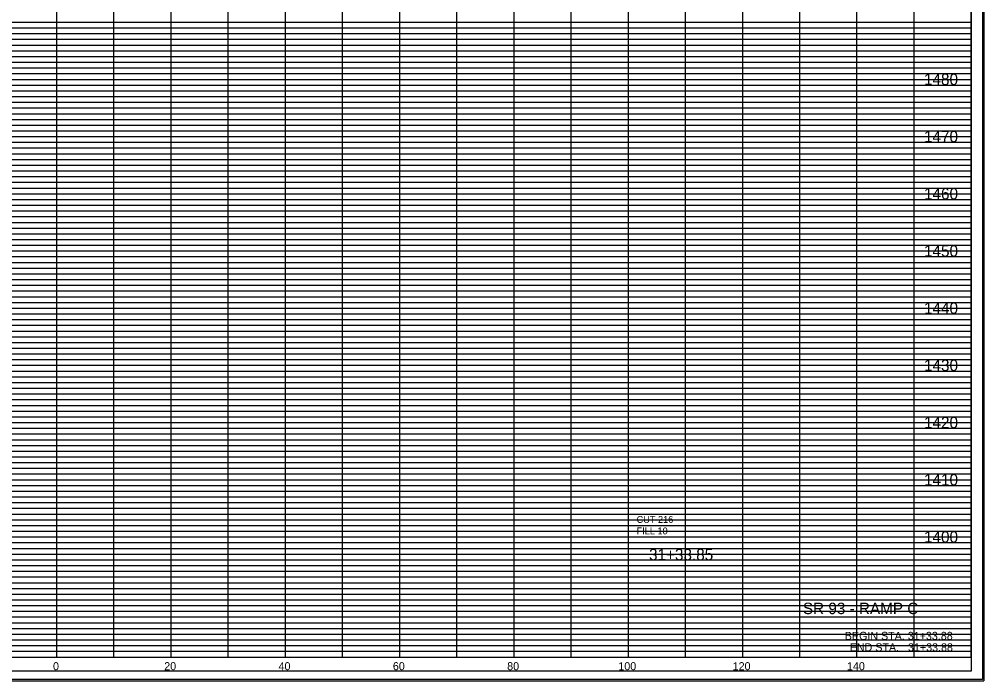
# Model space of a CAD drawing. Extents: x 980 to 2064, y 978 to 2267.
# Drawn here: x 1153.4 to 1322.2, y 1515.9 to 1631.5 of the extents above; entities that cross this region are included whole.
import ezdxf

# ---------------------------------------------------------------- set-up
doc = ezdxf.new("R2010")
doc.units = 0
for name, color, linetype in [('Default', 7, 'Continuous'), ('DESIGN - SHEET - Corner Text', 7, 'Continuous'), ('DESIGN - SHEET - Light Grid', 7, 'Continuous'), ('DESIGN - SHEET - Linework', 7, 'Continuous'), ('DESIGN - SHEET - Plot Shape', 7, 'Continuous'), ('DESIGN - TYPICAL - Text', 7, 'Continuous')]:
    doc.layers.add(name, color=color, linetype=linetype)

# ---------------------------------------------------------------- blocks, each defined once
blk = doc.blocks.new('XSTSHT')
at = {"layer": 'DESIGN - SHEET - Light Grid'}
for p, q in [((8, 11.1), (16, 11.1)), ((16, 11.1), (24, 11.1)), ((24, 11.1), (32, 11.1)), ((8, 10.9), (16, 10.9)), ((8, 10.8), (16, 10.8)), ((16, 10.9), (24, 10.9)), ((16, 10.8), (24, 10.8)), ((24, 10.9), (32, 10.9)), ((24, 10.8), (32, 10.8)), ((8, 10.7), (16, 10.7)), ((16, 10.7), (24, 10.7)), ((24, 10.7), (32, 10.7)), ((8, 10.6), (16, 10.6)), ((8, 10.5), (16, 10.5)), ((16, 10.6), (24, 10.6)), ((16, 10.5), (24, 10.5)), ((24, 10.6), (32, 10.6)), ((24, 10.5), (32, 10.5)), ((8, 10.4), (16, 10.4)), ((8, 10.3), (16, 10.3)), ((16, 10.4), (24, 10.4)), ((16, 10.3), (24, 10.3)), ((24, 10.4), (32, 10.4)), ((24, 10.3), (32, 10.3)), ((8, 10.2), (16, 10.2)), ((16, 10.2), (24, 10.2)), ((24, 10.2), (32, 10.2)), ((8, 10.1), (16, 10.1)), ((16, 10.1), (24, 10.1)), ((24, 10.1), (32, 10.1)), ((8, 9.9), (16, 9.9)), ((8, 9.8), (16, 9.8)), ((16, 9.9), (24, 9.9)), ((16, 9.8), (24, 9.8)), ((24, 9.9), (32, 9.9)), ((24, 9.8), (32, 9.8)), ((8, 9.7), (16, 9.7)), ((16, 9.7), (24, 9.7)), ((24, 9.7), (32, 9.7)), ((8, 9.6), (16, 9.6)), ((8, 9.5), (16, 9.5)), ((16, 9.6), (24, 9.6)), ((16, 9.5), (24, 9.5)), ((24, 9.6), (32, 9.6)), ((24, 9.5), (32, 9.5)), ((8, 9.4), (16, 9.4)), ((8, 9.3), (16, 9.3)), ((16, 9.4), (24, 9.4)), ((16, 9.3), (24, 9.3)), ((24, 9.4), (32, 9.4)), ((24, 9.3), (32, 9.3)), ((8, 9.2), (16, 9.2)), ((16, 9.2), (24, 9.2)), ((24, 9.2), (32, 9.2)), ((8, 9.1), (16, 9.1)), ((16, 9.1), (24, 9.1)), ((24, 9.1), (32, 9.1)), ((8, 8.9), (16, 8.9)), ((8, 8.8), (16, 8.8)), ((16, 8.9), (24, 8.9)), ((16, 8.8), (24, 8.8)), ((24, 8.9), (32, 8.9)), ((24, 8.8), (32, 8.8)), ((8, 8.7), (16, 8.7)), ((16, 8.7), (24, 8.7)), ((24, 8.7), (32, 8.7)), ((8, 8.6), (16, 8.6)), ((8, 8.5), (16, 8.5)), ((16, 8.6), (24, 8.6)), ((16, 8.5), (24, 8.5)), ((24, 8.6), (32, 8.6)), ((24, 8.5), (32, 8.5)), ((8, 8.4), (16, 8.4)), ((8, 8.3), (16, 8.3)), ((16, 8.4), (24, 8.4)), ((16, 8.3), (24, 8.3)), ((24, 8.4), (32, 8.4)), ((24, 8.3), (32, 8.3)), ((8, 8.2), (16, 8.2)), ((8, 8.1), (16, 8.1)), ((16, 8.2), (24, 8.2)), ((16, 8.1), (24, 8.1)), ((24, 8.2), (32, 8.2)), ((24, 8.1), (32, 8.1)), ((8, 7.9), (16, 7.9)), ((8, 7.8), (16, 7.8)), ((16, 7.9), (24, 7.9)), ((16, 7.8), (24, 7.8)), ((24, 7.9), (32, 7.9)), ((24, 7.8), (32, 7.8)), ((8, 7.7), (16, 7.7)), ((8, 7.6), (16, 7.6)), ((16, 7.7), (24, 7.7)), ((16, 7.6), (24, 7.6)), ((24, 7.7), (32, 7.7)), ((24, 7.6), (32, 7.6)), ((8, 7.5), (16, 7.5)), ((16, 7.5), (24, 7.5)), ((24, 7.5), (32, 7.5)), ((8, 7.4), (16, 7.4)), ((8, 7.3), (16, 7.3)), ((16, 7.4), (24, 7.4)), ((16, 7.3), (24, 7.3)), ((24, 7.4), (32, 7.4)), ((24, 7.3), (32, 7.3)), ((8, 7.2), (16, 7.2)), ((8, 7.1), (16, 7.1)), ((16, 7.2), (24, 7.2)), ((16, 7.1), (24, 7.1)), ((24, 7.2), (32, 7.2)), ((24, 7.1), (32, 7.1)), ((8, 6.9), (16, 6.9)), ((8, 6.8), (16, 6.8)), ((16, 6.9), (24, 6.9)), ((16, 6.8), (24, 6.8)), ((24, 6.9), (32, 6.9)), ((24, 6.8), (32, 6.8)), ((8, 6.7), (16, 6.7)), ((8, 6.6), (16, 6.6)), ((16, 6.7), (24, 6.7)), ((16, 6.6), (24, 6.6)), ((24, 6.7), (32, 6.7)), ((24, 6.6), (32, 6.6)), ((8, 6.5), (16, 6.5)), ((16, 6.5), (24, 6.5)), ((24, 6.5), (32, 6.5)), ((8, 6.4), (16, 6.4)), ((8, 6.3), (16, 6.3)), ((16, 6.4), (24, 6.4)), ((16, 6.3), (24, 6.3)), ((24, 6.4), (32, 6.4)), ((24, 6.3), (32, 6.3)), ((8, 6.2), (16, 6.2)), ((8, 6.1), (16, 6.1)), ((16, 6.2), (24, 6.2)), ((16, 6.1), (24, 6.1)), ((24, 6.2), (32, 6.2)), ((24, 6.1), (32, 6.1)), ((8, 5.9), (16, 5.9)), ((8, 5.8), (16, 5.8)), ((16, 5.9), (24, 5.9)), ((16, 5.8), (24, 5.8)), ((24, 5.9), (32, 5.9)), ((24, 5.8), (32, 5.8)), ((8, 5.7), (16, 5.7)), ((8, 5.6), (16, 5.6)), ((16, 5.7), (24, 5.7)), ((16, 5.6), (24, 5.6)), ((24, 5.7), (32, 5.7)), ((24, 5.6), (32, 5.6)), ((8, 5.5), (16, 5.5)), ((8, 5.4), (16, 5.4)), ((16, 5.5), (24, 5.5)), ((16, 5.4), (24, 5.4)), ((24, 5.5), (32, 5.5)), ((24, 5.4), (32, 5.4)), ((8, 5.3), (16, 5.3)), ((16, 5.3), (24, 5.3)), ((24, 5.3), (32, 5.3)), ((8, 5.2), (16, 5.2)), ((8, 5.1), (16, 5.1)), ((16, 5.2), (24, 5.2)), ((16, 5.1), (24, 5.1)), ((24, 5.2), (32, 5.2)), ((24, 5.1), (32, 5.1)), ((8, 4.9), (16, 4.9)), ((16, 4.9), (24, 4.9)), ((24, 4.9), (32, 4.9)), ((8, 4.8), (16, 4.8)), ((16, 4.8), (24, 4.8)), ((24, 4.8), (32, 4.8)), ((8, 4.7), (16, 4.7)), ((8, 4.6), (16, 4.6)), ((16, 4.7), (24, 4.7)), ((16, 4.6), (24, 4.6)), ((24, 4.7), (32, 4.7)), ((24, 4.6), (32, 4.6)), ((8, 4.5), (16, 4.5)), ((8, 4.4), (16, 4.4)), ((16, 4.5), (24, 4.5)), ((16, 4.4), (24, 4.4)), ((24, 4.5), (32, 4.5)), ((24, 4.4), (32, 4.4)), ((8, 4.3), (16, 4.3)), ((16, 4.3), (24, 4.3)), ((24, 4.3), (32, 4.3)), ((8, 4.2), (16, 4.2)), ((8, 4.1), (16, 4.1)), ((16, 4.2), (24, 4.2)), ((16, 4.1), (24, 4.1)), ((24, 4.2), (32, 4.2)), ((24, 4.1), (32, 4.1)), ((8, 3.9), (16, 3.9)), ((16, 3.9), (24, 3.9)), ((24, 3.9), (32, 3.9)), ((8, 3.8), (16, 3.8)), ((16, 3.8), (24, 3.8)), ((24, 3.8), (32, 3.8)), ((8, 3.7), (16, 3.7)), ((8, 3.6), (16, 3.6)), ((16, 3.7), (24, 3.7)), ((16, 3.6), (24, 3.6)), ((24, 3.7), (32, 3.7)), ((24, 3.6), (32, 3.6)), ((8, 3.5), (16, 3.5)), ((8, 3.4), (16, 3.4)), ((16, 3.5), (24, 3.5)), ((16, 3.4), (24, 3.4)), ((24, 3.5), (32, 3.5)), ((24, 3.4), (32, 3.4)), ((8, 3.3), (16, 3.3)), ((16, 3.3), (24, 3.3)), ((24, 3.3), (32, 3.3)), ((8, 3.2), (16, 3.2)), ((8, 3.1), (16, 3.1)), ((16, 3.2), (24, 3.2)), ((16, 3.1), (24, 3.1)), ((24, 3.2), (32, 3.2)), ((24, 3.1), (32, 3.1)), ((8, 2.9), (16, 2.9)), ((16, 2.9), (24, 2.9)), ((24, 2.9), (32, 2.9)), ((8, 2.8), (16, 2.8)), ((8, 2.7), (16, 2.7)), ((16, 2.8), (24, 2.8)), ((16, 2.7), (24, 2.7)), ((24, 2.8), (32, 2.8)), ((24, 2.7), (32, 2.7)), ((8, 2.6), (16, 2.6)), ((16, 2.6), (24, 2.6)), ((24, 2.6), (32, 2.6)), ((8, 2.5), (16, 2.5)), ((8, 2.4), (16, 2.4)), ((16, 2.5), (24, 2.5)), ((16, 2.4), (24, 2.4)), ((24, 2.5), (32, 2.5)), ((24, 2.4), (32, 2.4)), ((8, 2.3), (16, 2.3)), ((8, 2.2), (16, 2.2)), ((16, 2.3), (24, 2.3)), ((16, 2.2), (24, 2.2)), ((24, 2.3), (32, 2.3)), ((24, 2.2), (32, 2.2)), ((8, 2.1), (16, 2.1)), ((16, 2.1), (24, 2.1)), ((24, 2.1), (32, 2.1)), ((8, 1.9), (16, 1.9)), ((16, 1.9), (24, 1.9)), ((24, 1.9), (32, 1.9)), ((8, 1.8), (16, 1.8)), ((8, 1.7), (16, 1.7)), ((16, 1.8), (24, 1.8)), ((16, 1.7), (24, 1.7)), ((24, 1.8), (32, 1.8)), ((24, 1.7), (32, 1.7)), ((8, 1.6), (16, 1.6)), ((16, 1.6), (24, 1.6)), ((24, 1.6), (32, 1.6)), ((8, 1.5), (16, 1.5)), ((8, 1.4), (16, 1.4)), ((16, 1.5), (24, 1.5)), ((16, 1.4), (24, 1.4)), ((24, 1.5), (32, 1.5)), ((24, 1.4), (32, 1.4)), ((8, 1.3), (16, 1.3)), ((8, 1.2), (16, 1.2)), ((16, 1.3), (24, 1.3)), ((16, 1.2), (24, 1.2)), ((24, 1.3), (32, 1.3)), ((24, 1.2), (32, 1.2)), ((8, 1.1), (16, 1.1)), ((16, 1.1), (24, 1.1)), ((24, 1.1), (32, 1.1)), ((8, 0.9), (16, 0.9)), ((16, 0.9), (24, 0.9)), ((24, 0.9), (32, 0.9)), ((8, 0.8), (16, 0.8)), ((8, 0.7), (16, 0.7)), ((16, 0.8), (24, 0.8)), ((16, 0.7), (24, 0.7)), ((24, 0.8), (32, 0.8)), ((24, 0.7), (32, 0.7)), ((8, 0.6), (16, 0.6)), ((16, 0.6), (24, 0.6)), ((24, 0.6), (32, 0.6)), ((8, 0.5), (16, 0.5)), ((8, 0.4), (16, 0.4)), ((16, 0.5), (24, 0.5)), ((16, 0.4), (24, 0.4)), ((24, 0.5), (32, 0.5)), ((24, 0.4), (32, 0.4)), ((8, 0.3), (16, 0.3)), ((8, 0.2), (16, 0.2)), ((16, 0.3), (24, 0.3)), ((16, 0.2), (24, 0.2)), ((24, 0.3), (32, 0.3)), ((24, 0.2), (32, 0.2)), ((8, 0.1), (16, 0.1)), ((16, 0.1), (24, 0.1)), ((24, 0.1), (32, 0.1))]:
    blk.add_line(p, q, dxfattribs=at)
at = {"layer": 'DESIGN - SHEET - Linework'}
for p, q in [((32.217, 21.414), (32.217, -0.414)), ((16, 0), (16, 21)), ((17, 0), (17, 21)), ((18, 0), (18, 21)), ((19, 0), (19, 21)), ((20, 0), (20, 21)), ((21, 0), (21, 21)), ((22, 0), (22, 21)), ((23, 0), (23, 21)), ((24, 0), (24, 21)), ((25, 0), (25, 21)), ((26, 0), (26, 21)), ((27, 0), (27, 21)), ((28, 0), (28, 20)), ((29, 0), (29, 20)), ((30, 0), (30, 20)), ((31, 0), (31, 20)), ((0, 11), (32, 11)), ((0, 10), (32, 10)), ((0, 9), (32, 9)), ((0, 8), (32, 8)), ((0, 7), (32, 7)), ((0, 6), (32, 6)), ((0, 5), (32, 5)), ((0, 4), (32, 4)), ((0, 3), (32, 3)), ((0, 2), (32, 2)), ((0, 1), (32, 1)), ((-1.823, -0.414), (32.217, -0.414))]:
    blk.add_line(p, q, dxfattribs=at)
blk.add_lwpolyline([(0, 21), (0, 0), (32, 0), (32, 21), (0, 21)], dxfattribs=at)
at = {"layer": 'DESIGN - SHEET - Plot Shape'}
for points in [[(-1.803, 21.394), (32.197, 21.394), (32.197, -0.394), (-1.803, -0.394)], [(-0.85, 21), (32, 21), (32, -0.25), (-0.85, -0.25)]]:
    blk.add_lwpolyline(points, close=True, dxfattribs=at)

msp = doc.modelspace()

# ---------------------------------------------------------------- block references
at = {"layer": 'Default', "xscale": 10, "yscale": 10}
msp.add_blockref('XSTSHT', (1000, 1520), dxfattribs=at)

# ---------------------------------------------------------------- texts
at = {"layer": 'Default'}
for s, height, p in [('     1480     ', 2, (1308.01, 1620)), ('     1470     ', 2, (1308.01, 1610)), ('     1460     ', 2, (1308.01, 1600)), ('     1450     ', 2, (1308.01, 1590)), ('     1440     ', 2, (1308.01, 1580)), ('     1430     ', 2, (1308.01, 1570)), ('     1420     ', 2, (1308.01, 1560)), ('     1410     ', 2, (1308.01, 1550)), ('     1400     ', 2, (1308.01, 1540)), ('     31+33.85     ', 2, (1259.9, 1536.91)), ('     0     ', 1.4, (1156.74, 1517.7)), ('     0     ', 1.4, (1156.74, 1517.7)), ('     20     ', 1.4, (1176.2, 1517.7)), ('     40     ', 1.4, (1196.2, 1517.7)), ('     60     ', 1.4, (1216.2, 1517.7)), ('     80     ', 1.4, (1236.2, 1517.7)), ('     100     ', 1.4, (1255.65, 1517.7)), ('     120     ', 1.4, (1275.65, 1517.7)), ('     140     ', 1.4, (1295.65, 1517.7))]:
    msp.add_text(s, height=height, dxfattribs=at).set_placement(p)
at = {"layer": 'DESIGN - SHEET - Corner Text'}
for s, height, p in [('SR 93 - RAMP C', 2, (1290.53, 1527.5)), ('BEGIN STA. 31+33.88', 1.4, (1297.86, 1523)), ('END STA.   31+33.88', 1.4, (1298.73, 1521))]:
    msp.add_text(s, height=height, dxfattribs=at).set_placement(p)
at = {"layer": 'DESIGN - TYPICAL - Text'}
for s, p in [('CUT 216', (1261.44, 1543.45)), ('FILL 10', (1261.44, 1541.45))]:
    msp.add_text(s, height=1.2, dxfattribs=at).set_placement(p)

doc.saveas('drawing.dxf')
